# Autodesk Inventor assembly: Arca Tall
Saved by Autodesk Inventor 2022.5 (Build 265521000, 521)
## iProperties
Created: 2024-07
Part Number: Arca Tall
Document SubType Name: Assembly
Designer: AdminForWorker
Title: Arca Tall v16
Author: AdminForWorker
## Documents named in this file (2)
- z:\worker\convert-fusion-r03-cosv3\tmp\job-1\79\temp\files\3a003a07-c448-400c-9cf1-292e8316b43e\Arca Tall v16.iam
- z:\worker\convert-fusion-r03-cosv3\tmp\job-1\79\temp\files\3a003a07-c448-400c-9cf1-292e8316b43e\Arca Tall - Balon v3.3.ipt
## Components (1 placed, 1 different names)
1. Arca Tall - Balon v3.3:1
